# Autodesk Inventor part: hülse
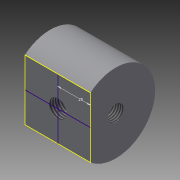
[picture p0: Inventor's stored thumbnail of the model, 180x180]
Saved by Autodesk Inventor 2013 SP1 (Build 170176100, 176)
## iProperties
Created: 2012-11
Part Number: hülse
Material: Allgemein
Document SubType Name: Modeling
Designer: macuser
Density: 1 g/cm^3
Author: macuser
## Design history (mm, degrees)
sketch "Skizze1"
  geometry: L1 (0, -42)-(0, 42) reference; L2 (-29.114, 0)-(39.852, 0) reference; L3 (-19.261, 23)-(-19.261, -23); A1 r 30 centre (0, 0) between (-19.261, -23) and (-19.261, 23); 1 further point
  constraints: 2 end point, 2 point on circle, 1 centre point, 1 coincident, 1 perpendicular
  dimensions: "d0" = 60 diameter of A1; "d2" = 46 distance of L3.end L3.start
extrude "Extrusion1" new body sketch "Skizze1" distance "d3" = 50; taper "d4" = 0 deg
sketch "Skizze3"
  geometry: L1 (0, 46)-(0, 0) reference; L2 (0, 0)-(50, 0) reference; L3 (50, 46)-(50, 0) reference; L4 (0, 46)-(50, 46) reference; L5 (0, 23)-(50, 23); L6 (25, 46)-(25, 0)
  constraints: 4 end point, 3 midpoint, 1 perpendicular
  dimensions: "d8" = 25 distance between parallel lines of L3 L6
hole "Bohrung1" diameter "d11" = 13.835; stored, may be unused: countersink angle "d15" = 90 deg, drill point angle "d17" = 118 deg; dims "d9" = 25, "d10" = 23, "d12" = 100, "d13" = 4, "d14" = 2, "d16" = 8
sketch "Skizze4"
  geometry: C1 r 6 at (0, 0); A1 r 30 centre (0, 0) between (23, -19.261) and (-23, -19.261) reference
  constraints: 1 centre point, 1 coincident
  dimensions: "d38" = 12 diameter of C1
extrude "Extrusion3" cut sketch "Skizze4" distance "d39" = 16; taper "d40" = 0 deg
feature "Gewinde1" dims "d41" = 10, "d42" = 0
sketch "Skizze5"
  geometry: C1 r 6 at (0, 0); A1 r 30 centre (0, 0) between (23, -19.261) and (-23, -19.261) reference
  constraints: 1 centre point, 1 coincident
  dimensions: "d43" = 12 diameter of C1
extrude "Extrusion4" cut sketch "Skizze5" distance "d44" = 16; taper "d45" = 0 deg
feature "Gewinde2" dims "d46" = 10, "d47" = 0
node "Volumenkörper1"
